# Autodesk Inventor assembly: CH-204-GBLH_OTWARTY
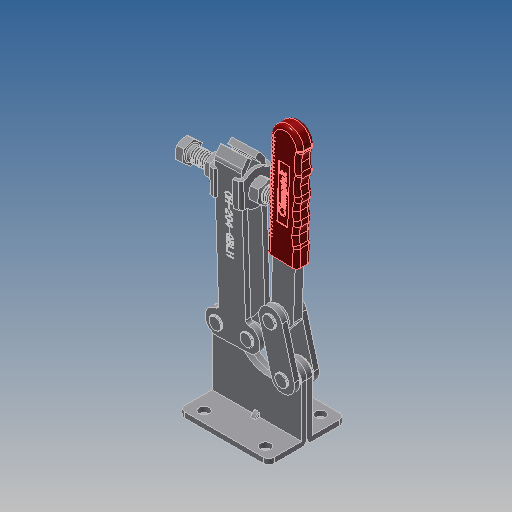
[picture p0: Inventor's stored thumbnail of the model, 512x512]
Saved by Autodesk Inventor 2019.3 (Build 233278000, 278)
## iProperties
Company: Î¢ÈíÖÐ¹ú
Created: 2012-09
Part Number: CH-204-GBLH_OTWARTY
Material: Ogólny
Description: STEP AP203
Document SubType Name: Assembly
Designer: CADENGINEERING4
Sending System: SolidWorks 2010
Preprocessor: SwSTEP 2.0
Title: CH-204-GBLH.STEP
Author: Î¢ÈíÓÃ»§
Revision Number: ÈÎºÎ
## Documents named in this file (11)
- E:\STRONA\Horizontal toggle clamp\CH-204-GBLH\CH-204-GBLH_OTWARTY.iam
- E:\STRONA\Horizontal toggle clamp\CH-204-GBLH\CH-FC-12300-01___.ipt
- E:\STRONA\Horizontal toggle clamp\CH-204-GBLH\204-GB-08___.ipt
- E:\STRONA\Horizontal toggle clamp\CH-204-GBLH\204-GB-05___.ipt
- E:\STRONA\Horizontal toggle clamp\CH-204-GBLH\204-GBLH-01___.ipt
- E:\STRONA\Horizontal toggle clamp\CH-204-GBLH\204-GB-06___.ipt
- E:\STRONA\Horizontal toggle clamp\CH-204-GBLH\204-GB-04___.ipt
- E:\STRONA\Horizontal toggle clamp\CH-204-GBLH\204-G-03___.iam
- E:\STRONA\Horizontal toggle clamp\CH-204-GBLH\FW120(2)___.ipt
- E:\STRONA\Horizontal toggle clamp\CH-204-GBLH\204-GBLH-02___.ipt
- E:\STRONA\Horizontal toggle clamp\CH-204-GBLH\CH-FC-12130___.ipt
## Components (22 placed, 22 different names)
1. CH-FC-12300-01____1 — Zestawiające:3, Zestawiające:6
2. 204-GB-08____2 — Zestawiające:23, Zestawiające:26
3. 204-GB-05____3 — Zestawiające:11, Zestawiające:12, Zestawiające:14
4. 204-GBLH-01____4 — Zestawiające:10, Zestawiające:11, Zestawiające:12, Zestawiające:13, Zestawiające:16, Zestawiające:17, Zestawiające:29, Zestawiające:30, Zestawiające:31, Zestawiające:32, Zestawiające:33, Kątowe:1
5. 204-GB-06____5 — Zestawiające:38, Zestawiające:40
6. 204-GB-04____6 — Zestawiające:15, Zestawiające:16, Zestawiające:18, Zestawiające:19, Zestawiające:21
7. 204-G-03____7 [sub-assembly] — Zestawiające:27, Zestawiające:28, Zestawiające:43, Kątowe:1
8. 204-GB-05____8 — Zestawiające:29, Zestawiające:32
9. FW120(2)____9 — Równoległe:1, Równoległe:2, Zestawiające:1, Zestawiające:7, Zestawiające:8
10. 204-GBLH-02____10 — Równoległe:1, Zestawiające:5, Zestawiające:8, Zestawiające:9, Zestawiające:34, Zestawiające:35, Zestawiające:36, Zestawiające:37, Zestawiające:38, Zestawiające:39, Zestawiające:40, Zestawiające:41, Zestawiające:42
11. 204-GB-08____11 — Zestawiające:24, Zestawiające:25, Zestawiające:28
12. 204-GB-06____12 — Zestawiające:19, Zestawiające:21
13. 204-GB-06____13 — Zestawiające:37, Zestawiające:39
14. 204-GB-08____14 — Zestawiające:41, Zestawiające:42, Zestawiające:43
15. 204-GB-08____15 — Zestawiające:33, Zestawiające:35, Zestawiające:36
16. 204-GB-06____16 — Zestawiające:20, Zestawiające:22, Zestawiające:27
17. 204-GB-05____17 — Zestawiające:10, Zestawiające:13, Zestawiające:15
18. CH-FC-12130____18 — Równoległe:3, Zestawiające:1, Zestawiające:2, Zestawiające:3, Zestawiające:4, Zestawiające:9
19. CH-FC-12300-01____19 — Równoległe:3, Zestawiające:2, Zestawiające:7
20. FW120(2)____20 — Równoległe:2, Zestawiające:4, Zestawiające:5, Zestawiające:6
21. 204-GB-05____21 — Zestawiające:30, Zestawiające:31, Zestawiające:34
22. 204-GB-04____22 — Zestawiające:14, Zestawiające:17, Zestawiające:18, Zestawiające:20, Zestawiające:22, Zestawiające:23, Zestawiające:24, Zestawiające:25, Zestawiające:26
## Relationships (47: Mate 43, Flush 3, Angle 1)
- Równoległe:1 [Flush]: FW120(2)____9 ↔ 204-GBLH-02____10
- Równoległe:2 [Flush]: FW120(2)____9 ↔ FW120(2)____20
- Równoległe:3 [Flush]: CH-FC-12130____18 ↔ CH-FC-12300-01____19
- Zestawiające:1 [Mate]: FW120(2)____9 ↔ CH-FC-12130____18
- Zestawiające:2 [Mate]: CH-FC-12130____18 ↔ CH-FC-12300-01____19
- Zestawiające:3 [Mate]: CH-FC-12300-01____1 ↔ CH-FC-12130____18
- Zestawiające:4 [Mate]: CH-FC-12130____18 ↔ FW120(2)____20
- Zestawiające:5 [Mate]: 204-GBLH-02____10 ↔ FW120(2)____20
- Zestawiające:6 [Mate]: CH-FC-12300-01____1 ↔ FW120(2)____20
- Zestawiające:7 [Mate]: FW120(2)____9 ↔ CH-FC-12300-01____19
- Zestawiające:8 [Mate]: FW120(2)____9 ↔ 204-GBLH-02____10
- Zestawiające:9 [Mate]: 204-GBLH-02____10 ↔ CH-FC-12130____18
- Zestawiające:10 [Mate]: 204-GBLH-01____4 ↔ 204-GB-05____17
- Zestawiające:11 [Mate]: 204-GB-05____3 ↔ 204-GBLH-01____4
- Zestawiające:12 [Mate]: 204-GB-05____3 ↔ 204-GBLH-01____4
- Zestawiające:13 [Mate]: 204-GBLH-01____4 ↔ 204-GB-05____17
- Zestawiające:14 [Mate]: 204-GB-05____3 ↔ 204-GB-04____22
- Zestawiające:15 [Mate]: 204-GB-04____6 ↔ 204-GB-05____17
- Zestawiające:16 [Mate]: 204-GBLH-01____4 ↔ 204-GB-04____6
- Zestawiające:17 [Mate]: 204-GBLH-01____4 ↔ 204-GB-04____22
- Zestawiające:18 [Mate]: 204-GB-04____6 ↔ 204-GB-04____22
- Zestawiające:19 [Mate]: 204-GB-04____6 ↔ 204-GB-06____12
- Zestawiające:20 [Mate]: 204-GB-06____16 ↔ 204-GB-04____22
- Zestawiające:21 [Mate]: 204-GB-04____6 ↔ 204-GB-06____12
- Zestawiające:22 [Mate]: 204-GB-06____16 ↔ 204-GB-04____22
- Zestawiające:23 [Mate]: 204-GB-08____2 ↔ 204-GB-04____22
- Zestawiające:24 [Mate]: 204-GB-08____11 ↔ 204-GB-04____22
- Zestawiające:25 [Mate]: 204-GB-08____11 ↔ 204-GB-04____22
- Zestawiające:26 [Mate]: 204-GB-08____2 ↔ 204-GB-04____22
- Zestawiające:27 [Mate]: 204-G-03____7 ↔ 204-GB-06____16
- Zestawiające:28 [Mate]: 204-G-03____7 ↔ 204-GB-08____11
- Zestawiające:29 [Mate]: 204-GBLH-01____4 ↔ 204-GB-05____8
- Zestawiające:30 [Mate]: 204-GBLH-01____4 ↔ 204-GB-05____21
- Zestawiające:31 [Mate]: 204-GBLH-01____4 ↔ 204-GB-05____21
- Zestawiające:32 [Mate]: 204-GBLH-01____4 ↔ 204-GB-05____8
- Zestawiające:33 [Mate]: 204-GBLH-01____4 ↔ 204-GB-08____15
- Zestawiające:34 [Mate]: 204-GBLH-02____10 ↔ 204-GB-05____21
- Zestawiające:35 [Mate]: 204-GBLH-02____10 ↔ 204-GB-08____15
- Zestawiające:36 [Mate]: 204-GBLH-02____10 ↔ 204-GB-08____15
- Zestawiające:37 [Mate]: 204-GBLH-02____10 ↔ 204-GB-06____13
- Zestawiające:38 [Mate]: 204-GB-06____5 ↔ 204-GBLH-02____10
- Zestawiające:39 [Mate]: 204-GBLH-02____10 ↔ 204-GB-06____13
- Zestawiające:40 [Mate]: 204-GB-06____5 ↔ 204-GBLH-02____10
- Zestawiające:41 [Mate]: 204-GBLH-02____10 ↔ 204-GB-08____14
- Zestawiające:42 [Mate]: 204-GBLH-02____10 ↔ 204-GB-08____14
- Zestawiające:43 [Mate]: 204-G-03____7 ↔ 204-GB-08____14
- Kątowe:1 [Angle]: 204-GBLH-01____4 ↔ 204-G-03____7
